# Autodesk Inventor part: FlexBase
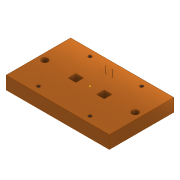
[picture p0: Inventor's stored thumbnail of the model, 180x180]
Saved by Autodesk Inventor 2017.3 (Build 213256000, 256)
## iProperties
Part Number: FlexBase
Material: ゴールド
Document SubType Name: モデリング
Designer: kyushu-hep
Density: 19.3 g/cm^3
Appearance: メタル 1600F 熱
Sheet Metal Rule: Default
Mass: 5352.02 g
Surface Area: 367.335 cm^2
Volume: 277.307 cm^3
Author: kyushu-hep
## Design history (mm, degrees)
sketch "スケッチ1"
  geometry: L1 (-112, 0)-(112, 0) reference; L2 (0, -70)-(0, 70) reference; L3 (80, -50)-(-80, -50); L4 (-80, -50)-(-80, 50); L5 (-80, 50)-(80, 50); L6 (80, 50)-(80, -50); L7 (80, -50)-(-80, 50); L8 (-80, -50)-(80, 50); 1 further point
  constraints: 12 end point, 2 midpoint, 2 parallel, 1 horizontal, 1 perpendicular
  dimensions: "d0" = 160 distance of L4.end L5.end; "d1" = 100 distance of L3.end L4.end
extrude "押し出し1" new body sketch "スケッチ1" distance "d2" = 20; taper "d3" = 0 deg
sketch "スケッチ12"
  geometry: L1 (-80, 50)-(-80, -50) reference; L2 (-80, -50)-(80, -50) reference; C1 r 0.5 at (-5.05, 29.5); C2 r 0.5 at (5.05, 29.5); 1 further point
  constraints: 2 centre point
  dimensions: "d66" = 1 diameter of C1; "d67" = 1 diameter of C2; "d130" = 10.1 distance of C2.centre C1.centre; "d133" = 29.5 vertical distance of point (0, 0) C2.centre; "d134" = 5.05 horizontal distance of C1.centre point (0, 0)
extrude "押し出し9" join sketch "スケッチ12" distance "d72" = 10; taper "d73" = 0 deg
sketch "スケッチ18"
  geometry: L1 (-80, 50)-(-80, -50) reference; L2 (-16, -6)-(-28, -6); L3 (-28, -6)-(-28, 6); L4 (-28, 6)-(-16, 6); L5 (-16, 6)-(-16, -6); L6 (-16, -6)-(-28, 6); L7 (-28, -6)-(-16, 6); L8 (80, -50)-(80, 50) reference; L9 (16, -6)-(28, -6); L10 (28, -6)-(28, 6); L11 (28, 6)-(16, 6); L12 (16, 6)-(16, -6); L13 (16, -6)-(28, 6); L14 (28, -6)-(16, 6); L15 (-80, -50)-(80, -50) reference; 3 further points
  constraints: 24 end point, 4 midpoint, 4 parallel, 2 equal length, 2 horizontal, 2 perpendicular, 1 collinear
  dimensions: "d108" = 16 distance from line of point (0, 0) L5; "d109" = 12 distance of L4.end L2.start; "d135" = 6 distance from line of point (0, 0) L2; "d151" = 12 distance of L2.start L2.end; "d152" = 16 distance from line of L12 point (0, 0)
extrude "押し出し15" cut sketch "スケッチ18" distance "d111" = 30; taper "d112" = 0 deg
sketch "スケッチ22"
  geometry: 1 further point
sketch "スケッチ23"
  geometry: C1 r 5 at (-70, 0); C2 r 5 at (70, 0); 1 further point
  constraints: 2 centre point
  dimensions: "d153" = 10 diameter of C1; "d154" = 10 diameter of C2; "d155" = 70 distance of point (0, 0) C1.centre; "d156" = 70 distance of point (0, 0) C2.centre
extrude "押し出し18" cut sketch "スケッチ23" distance "d157" = 10; taper "d158" = 0 deg
sketch "スケッチ24"
  geometry: C1 r 2.5 at (-40, 40); C2 r 2.5 at (40, 40); C3 r 2.5 at (-40, -40); C4 r 2.5 at (40, -40); 2 further points
  constraints: 4 centre point
  dimensions: "d159" = 5 diameter of C1; "d160" = 40 horizontal distance of C1.centre point (0, 0); "d161" = 40 horizontal distance of C1.centre point (0, 0); "d162" = 5 diameter of C2; "d163" = 40 horizontal distance of point (0, 0) C2.centre; "d164" = 40 horizontal distance of C2.centre point (0, 0); "d165" = 5 diameter of C3; "d166" = 40 horizontal distance of point (0, 0) C3.centre; "d167" = 40 horizontal distance of point (0, 0) C3.centre; "d168" = 5 diameter of C4; "d169" = 40 horizontal distance of point (0, 0) C4.centre; "d170" = 40 horizontal distance of point (0, 0) C4.centre
extrude "押し出し19" cut sketch "スケッチ24" distance "d171" = 20; taper "d172" = 0 deg
feature "ねじ4" dims "d173" = 10, "d174" = 0
feature "ねじ5" dims "d175" = 10, "d176" = 0
feature "ねじ6" dims "d177" = 10, "d178" = 0
feature "ねじ7" dims "d179" = 10, "d180" = 0
node "ソリッド1"
other parameters: "Thickness" = 0.5, "Kファクター" = 4.4, "BendRadius" = 0.5 (= Thickness), "BendReliefWidth" = 0.5 (= Thickness), "BendReliefDepth" = 0.25 (= 0.5 x Thickness), "CornerReliefSize" = 2 (= 4 x Thickness), "SeamGap" = 0.01, "MinimumRemnant" = 1 (= 2 x Thickness), "TransitionRadius" = 0.5 (= BendRadius), "JacobiRadiusSize" = 0.5 (= Thickness), "GapSize" = 0.5 (= Thickness)
